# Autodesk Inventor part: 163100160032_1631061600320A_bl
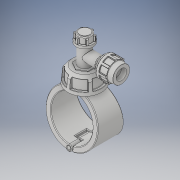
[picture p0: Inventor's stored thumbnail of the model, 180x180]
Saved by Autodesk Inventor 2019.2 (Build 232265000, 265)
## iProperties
Created: 2022-02
Part Number: 163100160032_1631061600320A_bl
Material: Generic
Description: Plassadle Tapper 125x32
Document SubType Name: Modeling
Designer: comp2
Density: 1 g/cm^3
Appearance: Default
Author: comp2
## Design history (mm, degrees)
derived "16310.ipt"
feature "Solid1::16310.ipt" dims "ScaleForDerivedMember" = 10
feature "Solid2::16310.ipt" dims "ScaleForDerivedMember" = 10
feature "Solid3::16310.ipt" dims "ScaleForDerivedMember" = 10
feature "Solid4::16310.ipt" dims "ScaleForDerivedMember" = 10
tag "TaggingFeature1"
body "Solid1"
body "Solid2"
body "Solid3"
body "Solid4"
other parameters: "d0" = 125 [user parameter], "d2" = 157 [user parameter], "d3" = 62.5 [user parameter], "d7" = 149.15 [user parameter], "d8" = 85 deg [user parameter], "d9" = 45 deg [user parameter], "d10" = 102 [user parameter], "d11" = 49 [user parameter], "d12" = 34.3 [user parameter], "d13" = 35.7 [user parameter], "d14" = 55.08 [user parameter], "d15" = 2.45 [user parameter], "d16" = 2 [user parameter], "d17" = 2 [user parameter], "d18" = 29.4 [user parameter], "d19" = 7.35 [user parameter], "d20" = 1 [user parameter], "d21" = 30.6 [user parameter], "d22" = 1 [user parameter], "d23" = 14.7 [user parameter], "d24" = 111 [user parameter], "d27" = 144 [user parameter], "d29" = 64 [user parameter], "d31" = 51.2 [user parameter], "d32" = 44.4 [user parameter], "d33" = 15.54 [user parameter], "d34" = 93 deg [user parameter], "d35" = 2 [user parameter], "d36" = 4 [user parameter], "d39" = 45 deg [user parameter], "d40" = 4 [user parameter], "d41" = 5 [user parameter], "d42" = 3.2 [user parameter], "d46" = 51 [user parameter], "d47" = 32 [user parameter], "d48" = 49 [user parameter], "d49" = 3.14 [user parameter], "d51" = 0 [user parameter], "d52" = 22.4 [user parameter], "d53" = 86.35 [user parameter], "d54" = 35 [user parameter], "d55" = 0 [user parameter], "d59" = 0 [user parameter], "d61" = 0 [user parameter], "d62" = 35 [user parameter], "d63" = 0 [user parameter], "d65" = 0 [user parameter], "d67" = 0 [user parameter], "d69" = 0 [user parameter], "d70" = 1 [user parameter], "d71" = 96 [user parameter], "d72" = 0 [user parameter], "d73" = 2 [user parameter], "d77" = 32 [user parameter], "d78" = 86.7 [user parameter], "d79" = 5.1 [user parameter], "d80" = 60 deg [user parameter], "d81" = 5.1 [user parameter], "d84" = 0 [user parameter], "d85" = 1 [user parameter], "d87" = 360 deg [user parameter], "d90" = 0 [user parameter], "d91" = 1 [user parameter], "d93" = 60 deg [user parameter], "d94" = 3.06 [user parameter], "d95" = 3.06 [user parameter], "d97" = 0 [user parameter], "d98" = 0.5 [user parameter], "d100" = 360 deg [user parameter], "d102" = 2 [user parameter], "d105" = 0 [user parameter], "d106" = 45 deg [user parameter], "d107" = 3.2 [user parameter], "d108" = 3.2 [user parameter], "d109" = 2.95332 [user parameter], "d110" = -8 [user parameter], "d112" = 0 [user parameter], "d113" = 0.5 [user parameter], "d115" = 360 deg [user parameter], "d117" = 0.5 [user parameter], "d" = 125 [user parameter], "d1" = 32 [user parameter], "B" = 157 [user parameter], "E_" = 64 [user parameter], "E1" = 102 [user parameter], "H2" = 144 [user parameter], "H3" = 111 [user parameter], "H_costum" = 49 [user parameter]
